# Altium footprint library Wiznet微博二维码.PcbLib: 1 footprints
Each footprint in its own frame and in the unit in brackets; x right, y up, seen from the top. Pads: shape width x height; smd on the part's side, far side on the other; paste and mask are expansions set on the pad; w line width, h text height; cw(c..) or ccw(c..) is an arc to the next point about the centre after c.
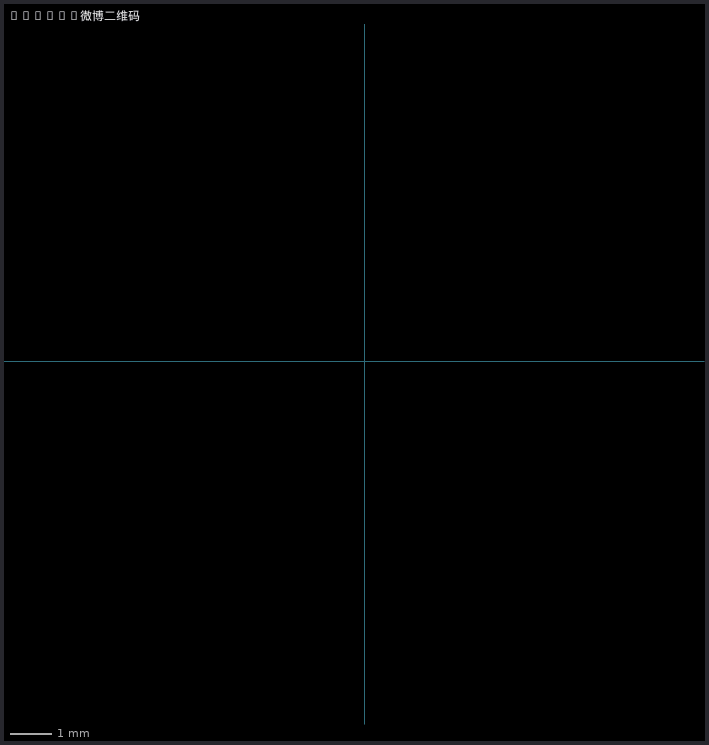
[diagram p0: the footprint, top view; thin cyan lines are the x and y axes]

## Wiznet微博二维码 [mm] "Wiznet微博二维码"
Bottom Overlay:
  drawing of 2130 lines, arcs and shapes, not listed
